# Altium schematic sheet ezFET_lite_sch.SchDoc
size 431 x 279 mm; Date: Not shown in title block; ApprovedBy: Not shown in title block; CheckedBy: Not shown in title block; Author: Not shown in title block; CompanyName: Not shown in title block; Engineer: Not shown in title block; Organization: Not shown in title block; Address1: Not shown in title block; Address2: Not shown in title block; Address3: Not shown in title block; Address4: Not shown in title block; DocumentNumber: 1; Revision: Use project parameter SCH_Rev; SheetNumber: 3; SheetTotal: 4; PageSetup: Record=PageOptions|CenterHorizontal=True|CenterVertical=True|PrintScale=1.00|XCorrection=1.00|YCorrection=1.00|PrintKind=0|BorderSize=5000000|LeftOffset=0|BottomOffset=0|Orientation=2|PaperLength=1000|PaperWidth=1000|Scale=100|PaperSource=15|PrintQuality=600|MediaType=1|DitherType=10|PaperKind=Letter|PrintScaleMode=1; Monkey Man: me
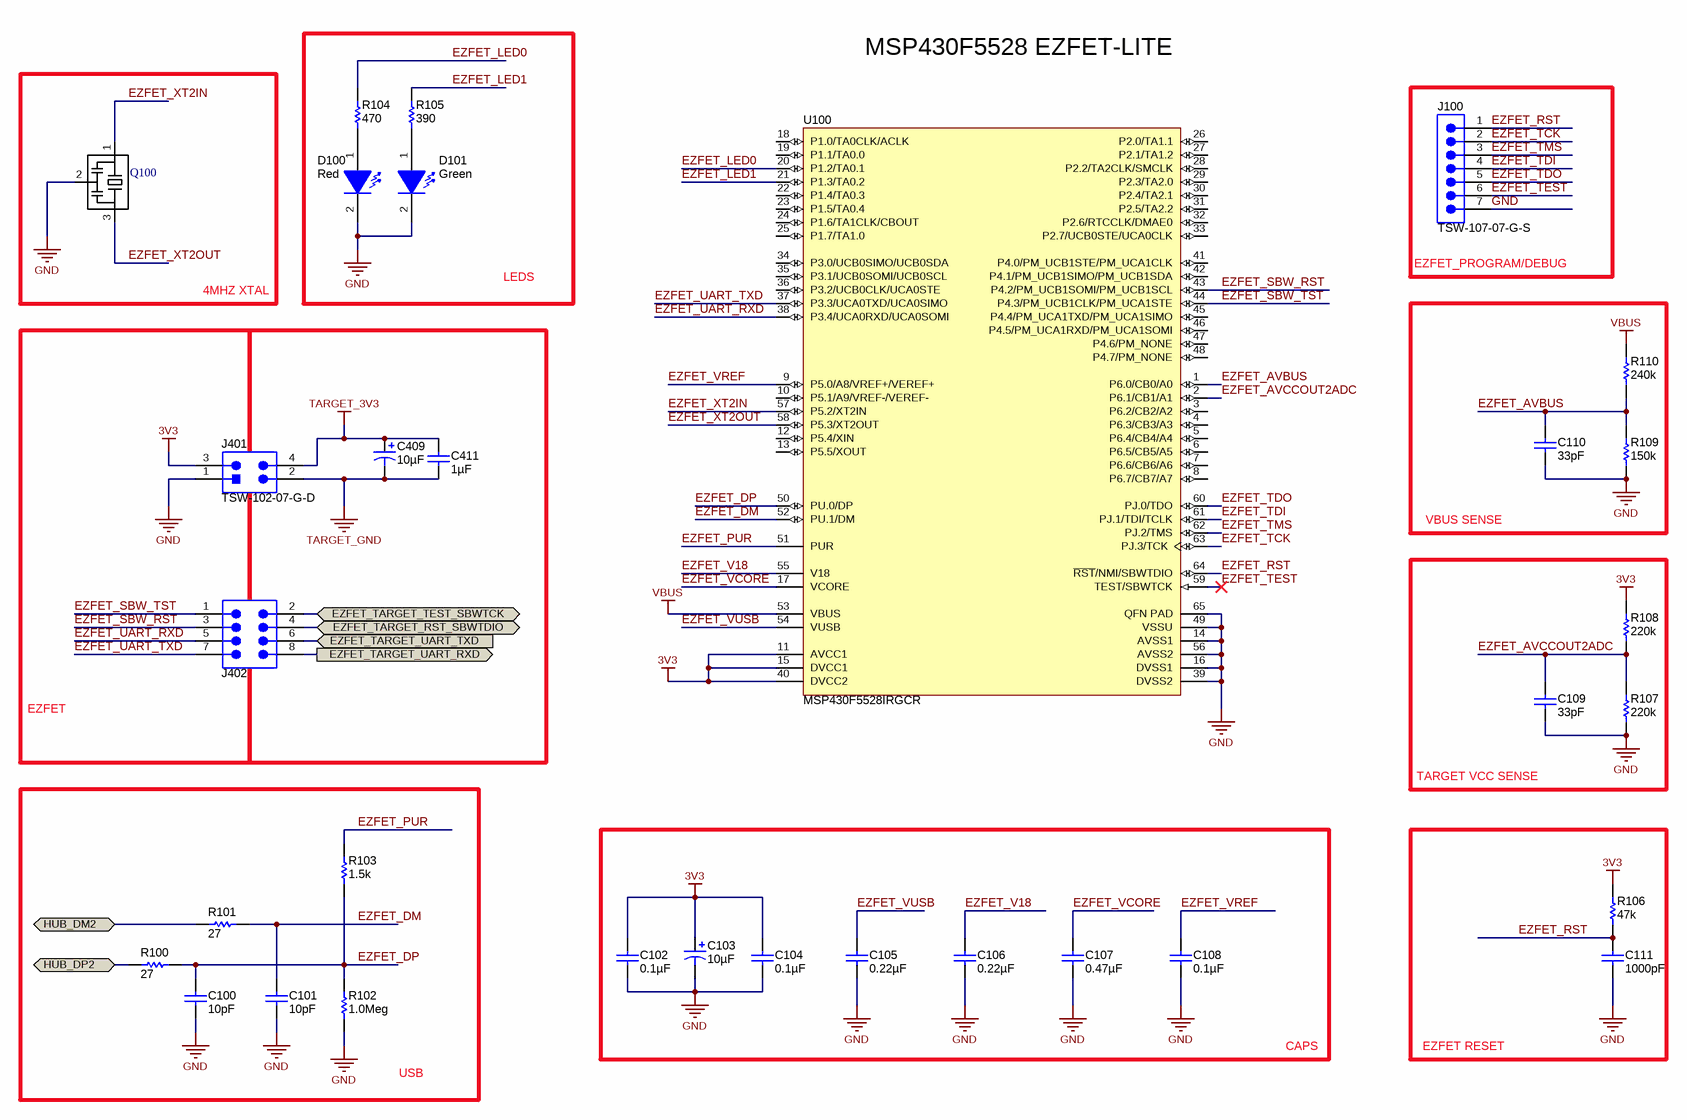
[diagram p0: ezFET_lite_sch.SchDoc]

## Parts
C100  ValueDisplayed: 10pF  [0402]  (hidden comment: 500R07S100JV4T)
C101  ValueDisplayed: 10pF  [0402]  (hidden comment: 500R07S100JV4T)
C102  ValueDisplayed: 0.1µF  [0402]  (hidden comment: C1005X5R1A104K)
C103  ValueDisplayed: 10µF  [3216-18]  (hidden comment: TPSA106M010R1800)
C104  ValueDisplayed: 0.1µF  [0402]  (hidden comment: C1005X5R1A104K)
C105  ValueDisplayed: 0.22µF  [0402]  (hidden comment: GRM155R61A224KE19D)
C106  ValueDisplayed: 0.22µF  [0402]  (hidden comment: GRM155R61A224KE19D)
C107  ValueDisplayed: 0.47µF  [0402]  (hidden comment: GRM155R61A474KE15D)
C108  ValueDisplayed: 0.1µF  [0402]  (hidden comment: C1005X5R1A104K)
C109  ValueDisplayed: 33pF  [0402]  (hidden comment: GRM1555C1H330JA01D)
C110  ValueDisplayed: 33pF  [0402]  (hidden comment: GRM1555C1H330JA01D)
C111  ValueDisplayed: 1000pF  [0402]  (hidden comment: C1005X7R1H102K)
C409  ValueDisplayed: 10µF  [3216-18]  (hidden comment: TPSA106M010R1800)
C411  ValueDisplayed: 1µF  [0603]  (hidden comment: C1608X7R1C105K)
D100  value Red  [LED_LTST-C190_Red]  (hidden comment: LTST-C190CKT)
D101  value Green  [LED_LTST-C190]  (hidden comment: LTST-C190GKT)
J100  TSW-107-07-G-S  [TSW-107-07-G-S]
J401  TSW-102-07-G-D  [TSW-102-07-G-D]
J402  TSW-104-07-G-D  [TSW-104-07-G-D]  (value not drawn)
Q100  MURATA-FILTER_CSTCR4M00G15  [CSTCR CERAMIC RESONATOR - MURATA]  (value not drawn)
R100  value 27  [0402]  (hidden comment: CRCW040227R0JNED)
R101  value 27  [0402]  (hidden comment: CRCW040227R0JNED)
R102  value 1.0Meg  [0402]  (hidden comment: CRCW04021M00JNED)
R103  value 1.5k  [0402]  (hidden comment: CRCW04021K30JNED)
R104  value 470  [0402]  (hidden comment: CRCW0402470RJNED)
R105  value 390  [0402]  (hidden comment: CRCW0402390RJNED)
R106  value 47k  [0402]  (hidden comment: CRCW040247K0JNED)
R107  value 220k  [0402]  (hidden comment: CRCW0402220KJNED)
R108  value 220k  [0402]  (hidden comment: CRCW0402220KJNED)
R109  value 150k  [0402]  (hidden comment: CRCW0402150KFKED)
R110  value 240k  [0402]  (hidden comment: CRCW0402240KJNED)
U100  MSP430F5528IRGCR  [TI_RGC0064B_N]

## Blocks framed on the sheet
LEDS: D100 D101 R104 R105
4MHZ XTAL: Q100
EZFET_PROGRAM/DEBUG: J100
VBUS SENSE: C110 R109 R110
TARGET VCC SENSE: C109 R107 R108
USB: C100 C101 R100-R103
CAPS: C102-C108
EZFET RESET: C111 R106

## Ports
EZFET_TARGET_RST_SBWTDIO (bidir), EZFET_TARGET_TEST_SBWTCK (bidir), EZFET_TARGET_UART_RXD (out), EZFET_TARGET_UART_TXD (in), HUB_DM2 (bidir), HUB_DP2 (bidir)

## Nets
3V3: C102.1 C103.1(+) C104.1 J401.3 R106.2 R108.2 U100.11(AVCC1) U100.15(DVCC1) U100.40(DVCC2)
GND: C100.2 C101.2 C102.2 C103.2(-) C104.2 C105.2 C106.2 C107.2 C108.2 C109.2 C110.2 C111.2 D100.2(K) D101.2(K) J100.7 J401.1 Q100.2 R102.2 R107.1 R109.1 U100.14(AVSS1) U100.16(DVSS1) U100.39(DVSS2) U100.49(VSSU) U100.56(AVSS2) U100.65(QFN_PAD)
TARGET_3V3: C409.1(+) C411.1 J401.4
TARGET_GND: C409.2(-) C411.2 J401.2
VBUS: R110.2 U100.53(VBUS)
EZFET_AVBUS: C110.1 R109.2 R110.1 U100.1(P6.0/CB0/A0)
EZFET_AVCCOUT2ADC: C109.1 R107.2 R108.1 U100.2(P6.1/CB1/A1)
EZFET_DM: C101.1 R101.2 U100.52(PU.1/DM)
EZFET_DP: C100.1 R100.2 R102.1 R103.2 U100.50(PU.0/DP)
EZFET_LED0: R104.2 U100.20(P1.2/TA0.1)
EZFET_LED1: R105.2 U100.21(P1.3/TA0.2)
EZFET_PUR: R103.1 U100.51(PUR)
EZFET_RST: C111.1 J100.1 R106.1 U100.64(~{RST}/NMI/SBWTDIO)
EZFET_SBW_RST: J402.3 U100.43(P4.2/PM_UCB1SOMI/PM_UCB1SCL)
EZFET_SBW_TST: J402.1 U100.44(P4.3/PM_UCB1CLK/PM_UCA1STE)
EZFET_TARGET_RST_SBWTDIO: J402.4 ; port EZFET_TARGET_RST_SBWTDIO
EZFET_TARGET_TEST_SBWTCK: J402.2 ; port EZFET_TARGET_TEST_SBWTCK
EZFET_TARGET_UART_RXD: J402.8 ; port EZFET_TARGET_UART_RXD
EZFET_TARGET_UART_TXD: J402.6 ; port EZFET_TARGET_UART_TXD
EZFET_TCK: J100.2 U100.63(PJ.3/TCK)
EZFET_TDI: J100.4 U100.61(PJ.1/TDI/TCLK)
EZFET_TDO: J100.5 U100.60(PJ.0/TDO)
EZFET_TEST: J100.6 U100.59(TEST/SBWTCK)
EZFET_TMS: J100.3 U100.62(PJ.2/TMS)
EZFET_UART_RXD: J402.5 U100.38(P3.4/UCA0RXD/UCA0SOMI)
EZFET_UART_TXD: J402.7 U100.37(P3.3/UCA0TXD/UCA0SIMO)
EZFET_V18: C106.1 U100.55(V18)
EZFET_VCORE: C107.1 U100.17(VCORE)
EZFET_VREF: C108.1 U100.9(P5.0/A8/VREF+/VEREF+)
EZFET_VUSB: C105.1 U100.54(VUSB)
EZFET_XT2IN: Q100.1 U100.57(P5.2/XT2IN)
EZFET_XT2OUT: Q100.3 U100.58(P5.3/XT2OUT)
HUB_DM2: R101.1 ; port HUB_DM2
HUB_DP2: R100.1 ; port HUB_DP2
NetD100_1: D100.1(A) R104.1
NetD101_1: D101.1(A) R105.1

Not connected (* = marked no-connect by the designer): U100 3(P6.2/CB2/A2) 4(P6.3/CB3/A3) 5(P6.4/CB4/A4) 6(P6.5/CB5/A5) 7(P6.6/CB6/A6) 8(P6.7/CB7/A7) 10(P5.1/A9/VREF-/VEREF-) 12(P5.4/XIN) 13(P5.5/XOUT) 18(P1.0/TA0CLK/ACLK) 19(P1.1/TA0.0) 22(P1.4/TA0.3) 23(P1.5/TA0.4) 24(P1.6/TA1CLK/CBOUT) 25(P1.7/TA1.0) 26(P2.0/TA1.1) 27(P2.1/TA1.2) 28(P2.2/TA2CLK/SMCLK) 29(P2.3/TA2.0) 30(P2.4/TA2.1) 31(P2.5/TA2.2) 32(P2.6/RTCCLK/DMAE0) 33(P2.7/UCB0STE/UCA0CLK) 34(P3.0/UCB0SIMO/UCB0SDA) 35(P3.1/UCB0SOMI/UCB0SCL) 36(P3.2/UCB0CLK/UCA0STE) 41(P4.0/PM_UCB1STE/PM_UCA1CLK) 42(P4.1/PM_UCB1SIMO/PM_UCB1SDA) 45(P4.4/PM_UCA1TXD/PM_UCA1SIMO) 46(P4.5/PM_UCA1RXD/PM_UCA1SOMI) 47(P4.6/PM_NONE) 48(P4.7/PM_NONE)

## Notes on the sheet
- MSP430F5528 EZFET-LITE
- EZFET

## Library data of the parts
C100 C101 = 500R07S100JV4T: CAP, CERM, 10pF, 50V, +/-5%, C0G/NP0, 0402; Manufacturer: Johanson Technology; Polarized: N; CompType: Capacitor; U/M: EA; Cap_F: 0.00000000001; Tolerance_%: 5; Value1: Unknown; VDC_V: 50; TaMin_C: -55; TaMax_C: 125
C102 C104 C108 = C1005X5R1A104K: CAP, CERM, 0.1uF, 10V, +/-10%, X5R, 0402; Manufacturer: TDK; Polarized: N; CompType: Capacitor; U/M: EA; Cap_F: 0.0000001; Tolerance_%: 10; ESR_Ohm: 0.0186; Value1: 0.0186 ohm; TaMin_C: -55; TaMax_C: 85
C103 = TPSA106M010R1800: CAP, TA, 10uF, 10V, +/-20%, 1.8 ohm, SMD; Manufacturer: AVX; Polarized: Y; CompType: Capacitor; U/M: EA; Cap_F: 0.00001; Tolerance_%: 20; Value1: 1.8 ohm; VDC_V: 10; ESR_Ohm: 1.8; IRMS_A: 0.184; TaMin_C: -55; TaMax_C: 125; Cap_Case: A
C105 C106 = GRM155R61A224KE19D: CAP, CERM, 0.22uF, 10V, +/-10%, X5R, 0402; Manufacturer: MuRata; Polarized: N; CompType: Capacitor; U/M: EA; Cap_F: 0.00000022; Tolerance_%: 10; Value1: Unknown; TaMin_C: -55; TaMax_C: 85
C107 = GRM155R61A474KE15D: CAP, CERM, 0.47uF, 10V, +/-10%, X5R, 0402; Manufacturer: MuRata; Polarized: N; CompType: Capacitor; U/M: EA; Cap_F: 0.00000047; Tolerance_%: 10; Value1: Unknown; TaMin_C: -55; TaMax_C: 85
C109 C110 = GRM1555C1H330JA01D: CAP, CERM, 33pF, 50V, +/-5%, C0G/NP0, 0402; Manufacturer: MuRata; Polarized: N; CompType: Capacitor; U/M: EA; Cap_F: 0.000000000033; Tolerance_%: 5; Value1: Unknown; VDC_V: 50; TaMin_C: -55; TaMax_C: 125
C111 = C1005X7R1H102K: CAP, CERM, 1000pF, 50V, +/-10%, X7R, 0402; Manufacturer: TDK; Polarized: N; CompType: Capacitor; U/M: EA; Cap_F: 0.000000001; Tolerance_%: 10; ESR_Ohm: 0.2381; Value1: 0.2381 ohm; VDC_V: 50; TaMin_C: -55; TaMax_C: 125
C409 = TPSA106M010R1800: CAP, TA, 10uF, 10V, +/-20%, 1.8 ohm, SMD; Manufacturer: AVX; Polarized: Y; CompType: Capacitor; U/M: EA; Cap_F: 0.00001; Tolerance_%: 20; ESR_Ohm: 1.8; Value1: 1.8 ohm; VDC_V: 10; IRMS_A: 0.184; TaMin_C: -55; TaMax_C: 125; Cap_Case: A
C411 = C1608X7R1C105K: CAP, CERM, 1uF, 16V, +/-10%, X7R, 0603; Manufacturer: TDK; Polarized: N; CompType: Capacitor; U/M: EA; Cap_F: 0.000001; Tolerance_%: 10; ESR_Ohm: 0.0057; Value1: 0.0057 ohm; VDC_V: 16; TaMin_C: -55; TaMax_C: 125
D100 = LTST-C190CKT: LED, Red, SMD; Manufacturer: Lite-On; Vf_V: 2; Value2: 2V; Io_A: 0.02; Tjmax_C: 85; Power_TotalModule: 0.0625; Value1: 0.0625W; U/M: EA
D101 = LTST-C190GKT: LED, Green, SMD; Manufacturer: Lite-On; Vf_V: 2.1; Value2: 2.1V; Io_A: 0.02; Power_TotalModule: 0.1; Value1: 0.1W; U/M: EA
J100 = TSW-107-07-G-S: Header, TH, 100mil, 7x1, Gold plated, (modified silk pin #1); Manufacturer: Samtec; U/M: EA
J401 = TSW-102-07-G-D: Header, TH, 100mil, 2x2, Gold plated, 230 mil above insulator; Manufacturer: Samtec; SymbolCreator: a0412235; U/M: EA
J402 = TSW-104-07-G-D: Header, TH, 100mil, 4x2, Gold plated, 230 mil above insulator; Manufacturer: Samtec; U/M: EA
Q100 = MURATA-FILTER_CSTCR4M00G15: Value Displayed: 4.00MHz
R100 R101 = CRCW040227R0JNED: RES, 27 ohm, 5%, 0.063W, 0402; Manufacturer: Vishay-Dale; CompType: Resistor; Value_Code: 27R0; Tolerance_%: 5; Power_W: 0.063; VDC_V: 50; TempCo: 200 ppm/C; EIA_Code: E24; U/M: EA
R102 = CRCW04021M00JNED: RES, 1.0Meg ohm, 5%, 0.063W, 0402; Manufacturer: Vishay-Dale; CompType: Resistor; Res_ohm: 1000000; Value_Code: 1M00; Tolerance_%: 5; Power_W: 0.063; VDC_V: 50; TempCo: 200 ppm/C; EIA_Code: E24; U/M: EA
R103 = CRCW04021K30JNED: RES, 1.3k ohm, 5%, 0.063W, 0402; Manufacturer: Vishay-Dale; CompType: Resistor; Res_ohm: 1300; Value_Code: 1k30; Tolerance_%: 5; Power_W: 0.063; VDC_V: 50; TempCo: 200 ppm/C; EIA_Code: E24; U/M: EA
R104 = CRCW0402470RJNED: RES, 470 ohm, 5%, 0.063W, 0402; Manufacturer: Vishay-Dale; CompType: Resistor; Value_Code: 470R; Tolerance_%: 5; Power_W: 0.063; VDC_V: 50; TempCo: 200 ppm/C; EIA_Code: E24; U/M: EA
R105 = CRCW0402390RJNED: RES, 390 ohm, 5%, 0.063W, 0402; Manufacturer: Vishay-Dale; CompType: Resistor; Value_Code: 390R; Tolerance_%: 5; Power_W: 0.063; VDC_V: 50; TempCo: 200 ppm/C; EIA_Code: E24; U/M: EA
R106 = CRCW040247K0JNED: RES, 47k ohm, 5%, 0.063W, 0402; Manufacturer: Vishay-Dale; CompType: Resistor; Res_ohm: 47000; Value_Code: 47k0; Tolerance_%: 5; Power_W: 0.063; VDC_V: 50; TempCo: 200 ppm/C; EIA_Code: E24; U/M: EA
R107 R108 = CRCW0402220KJNED: RES, 220k ohm, 5%, 0.063W, 0402; Manufacturer: Vishay-Dale; CompType: Resistor; Res_ohm: 220000; Tolerance_%: 5; Power_W: 0.063; VDC_V: 50; TempCo: 200 ppm/C; EIA_Code: E24; U/M: EA
R109 = CRCW0402150KFKED: RES, 150k ohm, 1%, 0.063W, 0402; Manufacturer: Vishay-Dale; CompType: Resistor; Res_ohm: 150000; Tolerance_%: 1; Power_W: 0.063; VDC_V: 50; TempCo: 100 ppm/C; EIA_Code: E96; U/M: EA
R110 = CRCW0402240KJNED: RES, 240k ohm, 5%, 0.063W, 0402; Manufacturer: Vishay-Dale; CompType: Resistor; Res_ohm: 240000; Tolerance_%: 5; Power_W: 0.063; VDC_V: 50; TempCo: 200 ppm/C; EIA_Code: E24; U/M: EA
U100 = MSP430F5528IRGCR: 25 MHz Mixed Signal Microcontroller with 128 KB Flash, 8192 B SRAM and 47 GPIOs, -40 to 85 degC, 64-pin QFN (RGC), Green (RoHS & no Sb/Br); Manufacturer: Texas Instruments; ADC: 12-bit SAR; ADC Channels: 16; Brown Out Reset: Yes; DMA: 3; Flash(KB): 128; Frequency(MHz): 25; GPIO: 47; Multiplier: 32x32; SRAM(B): 8192; SubFamily: 5 Series; Timers - 16-bit: 4; USB: 1; USCI_A (UART/LIN/IrDA/SPI): 2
